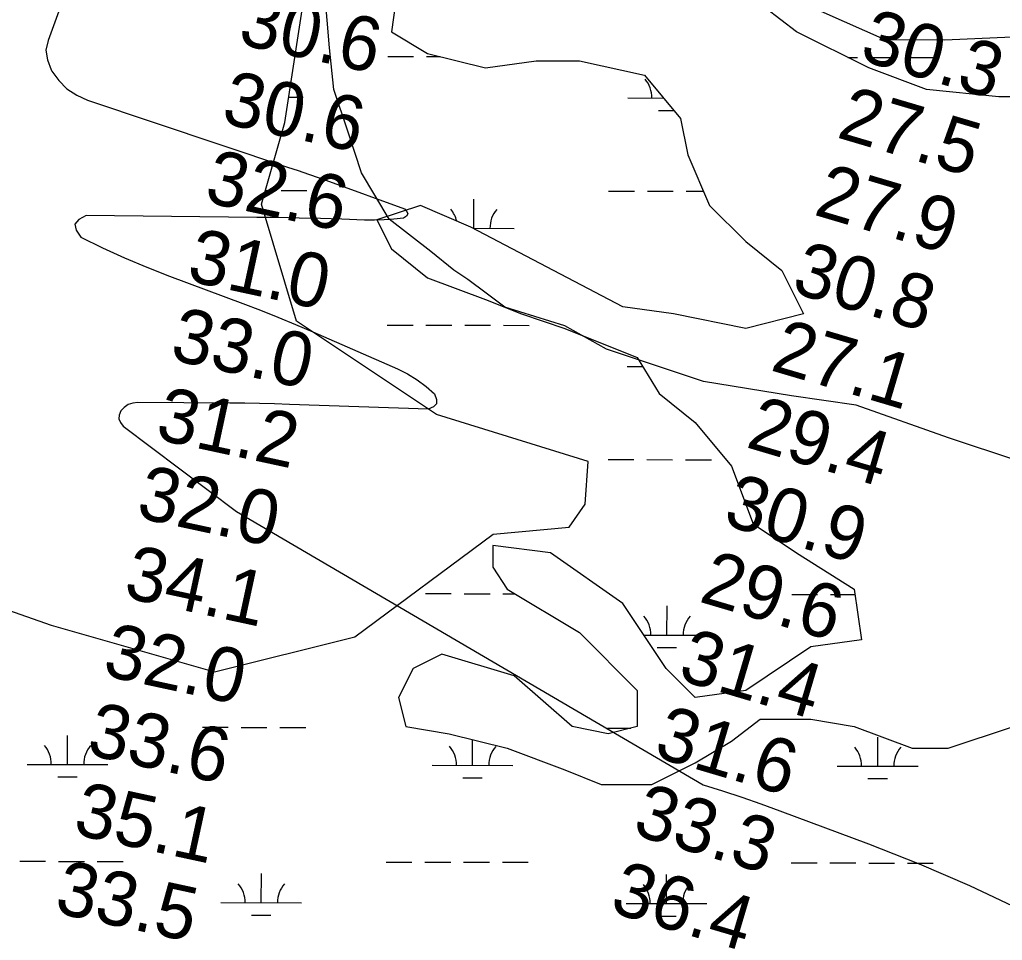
# Model space of a CAD drawing. Extents: x 3219052 to 3256913, y 800770 to 826146.
# Drawn here: x 3234446 to 3235663, y 813316 to 814457 of the extents above; entities that cross this region are included whole.
import ezdxf

# ---------------------------------------------------------------- set-up
doc = ezdxf.new("R2010")
doc.units = 0
for name, color, linetype in [('V-RIVR-RANG', 7, 'Continuous'), ('V-SITE-VEGE', 7, 'Continuous'), ('V-TOPO-MAJR', 7, 'Continuous'), ('V-TOPO-SHOR', 7, 'Continuous'), ('V-WETL-SWMP', 7, 'Continuous')]:
    doc.layers.add(name, color=color, linetype=linetype)

msp = doc.modelspace()

# ---------------------------------------------------------------- linework, layer by layer
at = {"layer": 'V-SITE-VEGE'}
for points in [[(3237209.3, 813984.9), (3237146.6, 814011.8), (3237119.7, 814029.7), (3237074.9, 814065.6), (3236967.4, 814155.2), (3236833, 814244.9), (3236770.2, 814271.8), (3236564.1, 814271.8), (3236492.5, 814280.8), (3236447.7, 814289.8), (3236223.6, 814271.8), (3235999.6, 814289.8), (3235919, 814307.7), (3235829.4, 814343.6), (3235739.8, 814361.5), (3235659.1, 814361.5), (3235569.5, 814370.5), (3235497.8, 814397.4), (3235408.2, 814442.2), (3235291.7, 814531.9)], [(3234915.4, 814505), (3234906.4, 814442.2), (3234951.2, 814415.3), (3235022.9, 814397.4), (3235085.6, 814406.3), (3235139.4, 814406.3), (3235220, 814388.4), (3235264.8, 814334.6), (3235273.8, 814289.8), (3235300.7, 814227), (3235345.5, 814182.1), (3235390.3, 814146.3), (3235417.2, 814092.5), (3235345.5, 814074.5), (3235255.9, 814092.5), (3235193.2, 814101.4), (3235005, 814200.1), (3234942.3, 814227), (3234888.5, 814209), (3234906.4, 814173.2), (3234951.2, 814137.3), (3235022.9, 814110.4), (3235067.7, 814092.5), (3235121.5, 814074.5), (3235211.1, 814038.7), (3235238, 813993.8), (3235282.8, 813958), (3235327.6, 813904.1), (3235354.5, 813832.4), (3235408.2, 813796.5), (3235479.9, 813751.7), (3235488.9, 813688.9), (3235426.1, 813680), (3235345.5, 813626.2), (3235282.8, 813617.2), (3235246.9, 813653.1), (3235193.2, 813733.8), (3235103.6, 813796.5), (3235031.9, 813805.5), (3235031.9, 813778.6), (3235049.8, 813751.7), (3235139.4, 813697.9), (3235211.1, 813626.2), (3235211.1, 813581.3), (3235175.2, 813572.3), (3235130.4, 813581.3), (3235058.7, 813644.1), (3234969.1, 813671), (3234933.3, 813653.1), (3234915.4, 813617.2), (3234924.3, 813581.3), (3234978.1, 813572.3), (3235049.8, 813554.4), (3235121.5, 813527.5), (3235166.3, 813509.6), (3235229, 813509.6), (3235282.8, 813536.5), (3235327.6, 813563.4), (3235363.4, 813590.3), (3235426.1, 813590.3), (3235479.9, 813581.3), (3235551.6, 813554.4), (3235596.4, 813554.4), (3235677, 813581.3)]]:
    msp.add_lwpolyline(points, dxfattribs=at)
at = {"layer": 'V-TOPO-MAJR'}
msp.add_lwpolyline([(3234514.2, 814522.6), (3234481.1, 814431.5), (3234478.5, 814419.5), (3234480.2, 814407.3), (3234484.7, 814395), (3234485.6, 814393.5), (3234494.4, 814381.8), (3234504.5, 814371.6), (3234516.6, 814363.8), (3234530, 814357.6), (3234777.8, 814274.6), (3234790.8, 814270.2), (3234803.8, 814265.7), (3234816.8, 814261.1), (3234829.7, 814256.5), (3234922.8, 814222.7), (3234925.7, 814219.5), (3234926.7, 814216.5), (3234925, 814213.8), (3234921.6, 814211.2), (3234909.5, 814210), (3234897.4, 814209.1), (3234885.3, 814208.8), (3234873.1, 814208.9), (3234844.9, 814209.9), (3234818.6, 814210.7), (3234792.3, 814211.4), (3234766, 814211.9), (3234739.7, 814212.2), (3234528.2, 814214.4), (3234519.2, 814209.5), (3234514.3, 814203.6), (3234515.9, 814196.2), (3234521.6, 814187.7), (3234548.6, 814174.4), (3234575.9, 814161.9), (3234603.6, 814150.3), (3234631.6, 814139.3), (3234722.3, 814105.5), (3234744.2, 814097.1), (3234765.9, 814088.5), (3234787.5, 814079.6), (3234809, 814070.4), (3234913.9, 814024.5), (3234926.4, 814018.2), (3234938.3, 814011), (3234949.4, 814002.6), (3234960, 813993.4), (3234962.4, 813986.7), (3234962.4, 813981.2), (3234958.4, 813977.3), (3234951.9, 813974.5), (3234780.2, 813980.5), (3234761.7, 813981), (3234743.2, 813981.5), (3234724.7, 813981.8), (3234706.2, 813982), (3234592.3, 813983), (3234586.1, 813982.1), (3234580.4, 813980.2), (3234575.5, 813976.8), (3234571.2, 813972.4), (3234569.2, 813967.3), (3234568.7, 813962.4), (3234570.6, 813957.9), (3234574, 813953.6), (3234714.7, 813847.8), (3235292.8, 813509), (3235316.7, 813501.6), (3235340.5, 813493.9), (3235364.2, 813485.6), (3235387.8, 813477.1), (3235497.6, 813436), (3235560.5, 813411.1), (3235622.6, 813384.5), (3235683.6, 813355.4)], dxfattribs=at)
at = {"layer": 'V-TOPO-SHOR'}
for points in [[(3235362.9, 814501.5), (3235517.6, 814432.4), (3235592.1, 814432.2), (3235712.5, 814437.7), (3235809.9, 814426), (3235867.2, 814414.4), (3235890, 814380), (3235907.1, 814339.8), (3235941.5, 814311.1), (3236010.3, 814316.7), (3236090.6, 814356.6), (3236148, 814390.9), (3236199.6, 814408), (3236262.7, 814407.9), (3236302.8, 814402), (3236348.6, 814379), (3236377.1, 814327.4), (3236382.8, 814275.8), (3236417.1, 814235.6), (3236445.7, 814218.3), (3236669.1, 814131.9), (3236753.1, 814131.7)], [(3235682.7, 813910.4), (3235596.8, 813939.2), (3235482.2, 813979.6), (3235402, 813991.2), (3235293.1, 814008.7), (3235172.8, 814049), (3235121.3, 814077.8), (3235046.8, 814100.9), (3235023.9, 814118.1), (3235001.1, 814135.4), (3234983.9, 814146.9), (3234955.3, 814169.9), (3234903.8, 814210.1), (3234869.5, 814267.5), (3234852.4, 814319.1), (3234835.3, 814370.7), (3234829.7, 814422.3), (3234824.1, 814491.1)]]:
    msp.add_lwpolyline(points, dxfattribs=at)
at = {"layer": 'V-WETL-SWMP'}
for p, q in [((3234902, 814411.5), (3234934, 814411.4)), ((3234950, 814411.4), (3234966.9, 814411.4)), ((3235471.9, 814410.3), (3235483.9, 814410.3)), ((3235499.9, 814410.2), (3235531.9, 814410.2)), ((3235547.9, 814410.1), (3235579.9, 814410.1)), ((3234779, 814361), (3234797.3, 814361)), ((3235199.2, 814360.1), (3235243.6, 814360)), ((3235237.2, 814344.6), (3235256.5, 814344.6)), ((3234750.2, 814245.6), (3234753.7, 814245.6)), ((3234769.7, 814245.6), (3234801.7, 814245.5)), ((3235175.6, 814244.7), (3235207.6, 814244.7)), ((3235223.6, 814244.6), (3235255.6, 814244.6)), ((3235271.6, 814244.5), (3235293.2, 814244.5)), ((3235008.4, 814198.7), (3235008.5, 814234.7)), ((3235007.6, 814198.7), (3235058.4, 814198.6)), ((3234901.3, 814078.8), (3234933.3, 814078.8)), ((3234949.3, 814078.7), (3234981.3, 814078.7)), ((3234997.3, 814078.6), (3235029.3, 814078.6)), ((3235045.3, 814078.5), (3235077.3, 814078.4)), ((3235198.5, 814027.5), (3235217.8, 814027.4)), ((3235174.9, 813912.1), (3235206.9, 813912)), ((3235222.9, 813912), (3235254.9, 813911.9)), ((3235270.9, 813911.9), (3235302.9, 813911.8)), ((3234948.6, 813746), (3234980.6, 813746)), ((3234996.6, 813745.9), (3235028.6, 813745.9)), ((3235044.6, 813745.8), (3235059.6, 813745.8)), ((3235402.5, 813745.1), (3235434.5, 813745)), ((3235450.5, 813745), (3235480.9, 813744.9)), ((3235247.8, 813694.7), (3235247.9, 813730.7)), ((3235219.1, 813694.7), (3235297.8, 813694.6)), ((3235235.8, 813679.3), (3235259.8, 813679.2)), ((3234505.1, 813534.4), (3234505.2, 813570.4)), ((3234672.3, 813580.5), (3234704.3, 813580.4)), ((3234720.3, 813580.3), (3234752.3, 813580.3)), ((3234768.3, 813580.2), (3234800.3, 813580.2)), ((3235174.2, 813579.4), (3235203.2, 813579.3)), ((3235007, 813533.3), (3235007.1, 813565.1)), ((3235508.9, 813532.3), (3235509, 813568.3)), ((3234455.1, 813534.5), (3234555.1, 813534.3)), ((3234957, 813533.4), (3235057, 813533.2)), ((3235458.9, 813532.4), (3235558.9, 813532.2)), ((3234493.1, 813519), (3234517.1, 813518.9)), ((3234995, 813517.9), (3235019, 813517.9)), ((3235496.9, 813516.9), (3235520.9, 813516.8)), ((3234446, 813414.4), (3234478, 813414.4)), ((3234494, 813414.3), (3234526, 813414.3)), ((3234542, 813414.2), (3234574, 813414.2)), ((3234899.9, 813413.5), (3234931.9, 813413.4)), ((3234947.9, 813413.4), (3234979.9, 813413.3)), ((3234995.9, 813413.3), (3235027.9, 813413.2)), ((3235043.9, 813413.2), (3235075.9, 813413.1)), ((3235401.8, 813412.4), (3235433.8, 813412.4)), ((3235449.8, 813412.3), (3235481.8, 813412.3)), ((3235497.8, 813412.2), (3235529.8, 813412.2)), ((3235545.8, 813412.1), (3235577.8, 813412.1)), ((3234745.2, 813363.1), (3234745.3, 813399.1)), ((3235247.1, 813362), (3235247.2, 813398)), ((3234695.2, 813363.2), (3234795.2, 813362.9)), ((3235197.1, 813362.1), (3235297.1, 813361.9)), ((3234733.2, 813347.6), (3234757.2, 813347.6)), ((3235235.1, 813346.6), (3235259.1, 813346.5))]:
    msp.add_line(p, q, dxfattribs=at)
for points in [[(3237209.3, 813984.9), (3237146.6, 814011.8), (3237119.7, 814029.7), (3237074.9, 814065.6), (3236967.4, 814155.2), (3236833, 814244.9), (3236770.2, 814271.8), (3236564.1, 814271.8), (3236492.5, 814280.8), (3236447.7, 814289.8), (3236223.6, 814271.8), (3235999.6, 814289.8), (3235919, 814307.7), (3235829.4, 814343.6), (3235739.8, 814361.5), (3235659.1, 814361.5), (3235569.5, 814370.5), (3235497.8, 814397.4), (3235408.2, 814442.2), (3235291.7, 814531.9)], [(3232589.1, 814286.4), (3233211.4, 813982.2), (3233471.9, 813837.4), (3233703.4, 813779.5), (3233963.9, 813779.5), (3234195.4, 813808.4), (3234484.8, 813707.1), (3234687.4, 813649.1), (3234861, 813692.6), (3235032.7, 813819.8), (3235126.6, 813828.4), (3235146.4, 813856.8), (3235150.4, 813909.8), (3234962.3, 813967.8), (3234788.7, 814083.6), (3234745.3, 814228.5), (3234774.2, 814329.8), (3234803.2, 814518.1)], [(3234915.4, 814505), (3234906.4, 814442.2), (3234951.2, 814415.3), (3235022.9, 814397.4), (3235085.6, 814406.3), (3235139.4, 814406.3), (3235220, 814388.4), (3235264.8, 814334.6), (3235273.8, 814289.8), (3235300.7, 814227), (3235345.5, 814182.1), (3235390.3, 814146.3), (3235417.2, 814092.5), (3235345.5, 814074.5), (3235255.9, 814092.5), (3235193.2, 814101.4), (3235005, 814200.1), (3234942.3, 814227), (3234888.5, 814209), (3234906.4, 814173.2), (3234951.2, 814137.3), (3235022.9, 814110.4), (3235067.7, 814092.5), (3235121.5, 814074.5), (3235211.1, 814038.7), (3235238, 813993.8), (3235282.8, 813958), (3235327.6, 813904.1), (3235354.5, 813832.4), (3235408.2, 813796.5), (3235479.9, 813751.7), (3235488.9, 813688.9), (3235426.1, 813680), (3235345.5, 813626.2), (3235282.8, 813617.2), (3235246.9, 813653.1), (3235193.2, 813733.8), (3235103.6, 813796.5), (3235031.9, 813805.5), (3235031.9, 813778.6), (3235049.8, 813751.7), (3235139.4, 813697.9), (3235211.1, 813626.2), (3235211.1, 813581.3), (3235175.2, 813572.3)], [(3235175.2, 813572.3), (3235130.4, 813581.3), (3235058.7, 813644.1), (3234969.1, 813671), (3234933.3, 813653.1), (3234915.4, 813617.2), (3234924.3, 813581.3), (3234978.1, 813572.3), (3235049.8, 813554.4), (3235121.5, 813527.5), (3235166.3, 813509.6), (3235229, 813509.6), (3235282.8, 813536.5), (3235327.6, 813563.4), (3235363.4, 813590.3), (3235426.1, 813590.3), (3235479.9, 813581.3), (3235551.6, 813554.4), (3235596.4, 813554.4), (3235677, 813581.3), (3235757.7, 813581.3), (3235856.3, 813554.4), (3235945.9, 813473.7)]]:
    msp.add_lwpolyline(points, dxfattribs=at)
for centre, start, end in [((3235194, 814360.6), 359.1081, 40.6518), ((3234953.2, 814199.3), 13.687, 40.6518), ((3235063.7, 814199), 139.1081, 180.6517), ((3235192.6, 813695.3), 359.1081, 40.6518), ((3235303.1, 813695), 139.1081, 180.6517), ((3234449.9, 813535), 359.1081, 40.6518), ((3234560.4, 813534.7), 139.1081, 180.6517), ((3234951.8, 813533.9), 359.1081, 40.6518), ((3235062.3, 813533.7), 139.1081, 180.6517), ((3235453.7, 813532.9), 359.1081, 40.6518), ((3235564.2, 813532.6), 139.1081, 180.6517), ((3234690, 813363.6), 359.1081, 40.6518), ((3234800.5, 813363.4), 139.1081, 180.6517), ((3235191.9, 813362.6), 359.1081, 40.6518), ((3235302.4, 813362.4), 139.1081, 180.6517)]:
    msp.add_arc(centre, 35.2, start, end, dxfattribs=at)

# ---------------------------------------------------------------- texts
at = {"layer": 'V-RIVR-RANG'}
for s, rotation, p in [('30.6', 347.8183, (3234714.9, 814427.2)), ('30.3', 343.5183, (3235484.8, 814407.7)), ('30.6', 347.8183, (3234694.1, 814329.4)), ('27.5', 343.5183, (3235456.6, 814311.7)), ('32.6', 347.8183, (3234673.2, 814231.6)), ('27.9', 343.5183, (3235428.2, 814215.9)), ('31.0', 347.8183, (3234651.3, 814134.1)), ('30.8', 343.5183, (3235400.3, 814119.8)), ('33.0', 347.8183, (3234630.5, 814036.3)), ('27.1', 343.5183, (3235374.5, 814023.2)), ('31.2', 347.8183, (3234612.4, 813937.8)), ('29.4', 343.5183, (3235344.1, 813927.9)), ('32.0', 347.8183, (3234588.7, 813840.7)), ('30.9', 343.5183, (3235315.7, 813832)), ('34.1', 347.8183, (3234573, 813741.7)), ('29.6', 343.5183, (3235286, 813736.5)), ('32.0', 347.8183, (3234547, 813645.1)), ('31.4', 343.5183, (3235259.7, 813640)), ('33.6', 347.8183, (3234527.2, 813547)), ('31.6', 343.5183, (3235229.7, 813544.6)), ('35.1', 347.8183, (3234510.4, 813448.3)), ('33.3', 343.5183, (3235203.4, 813448.1)), ('33.5', 347.8183, (3234487.3, 813351.1)), ('36.4', 343.5183, (3235175.2, 813352.1))]:
    msp.add_text(s, height=67, rotation=rotation, dxfattribs=at).set_placement(p)

doc.saveas('drawing.dxf')
